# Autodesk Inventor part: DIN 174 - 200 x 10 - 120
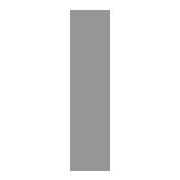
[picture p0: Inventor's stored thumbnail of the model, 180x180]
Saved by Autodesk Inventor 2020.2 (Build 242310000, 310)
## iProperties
_CCFamilyMember: 356
_CCFamilyDisplayName: DIN EN 10278 - Flachstahl
_FrameMemberDoc: Frame Member File
_Version: 15.0.0
_GetPNFromCC: 1
IsCustomPart: 1
Created: 2019-01
Part Number: DIN 174 - 200 x 10 - 120
Material: Stahl, weich
Description: Flachstahl
Document SubType Name: Modeling
Standard: DIN
Designer: lutzd
Standards Organization: DIN
Language: de-DE
Size Designation: 200 x 10
Categories: <MemberInstance><Categories><Category DisplayName="Profile" InternalName="089c4875-fa83-4c05-b084-43b9cc11f5ed" Mnemonic="GRDR"><CategoryParameter DisplayName="
Stock Number: 200 x 10
Mass: 1836.44 g
Surface Area: 533.912 cm^2
Volume: 233.941 cm^3
Density: 7.85 g/cm^3
Appearance: Semi-Polished(8)
G_L: 120,000 mm
G_W: 10,000 mm
G_H: 200,000 mm
+550D6204-CB8D-4930-8D8D-F81F26F66AC1+SCHNITTDETAIL1: Schnittwinkel 90,00 grd
DocNumber: ADSK-014385
Folder: .
Mass: 1,836 kg
VLT_Material: Stahl, weich
Dimensions: 200x10x120 mm
Title: Profil-Bauteil
Author: lutzd
Revision Number: -
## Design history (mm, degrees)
node "Startebene"
node "Endebene"
sketch "Skizze"
  geometry: L1 (5, -100)-(-5, -100); L2 (-5, -100)-(-5, 100); L3 (-5, 100)-(5, 100); L4 (5, 100)-(5, -100); L5 (-6, 0)-(8, 0); L6 (0, -30)-(0, 40); L7 (0, 140)-(0, -140) reference; L8 (-9.2, 0)-(13.2, 0) reference
  constraints: 12 end point, 2 collinear, 2 parallel, 1 horizontal, 1 perpendicular
  dimensions: "d0" = 200 distance between parallel lines of L3 L1 (= G_W); "d1" = 10 distance between parallel lines of L4 L2 (= G_H); "d4" = 5 distance between parallel lines of L6 L4 (= 0.5 x d1); "d5" = 100 distance between parallel lines of L5 L3 (= 0.5 x d0)
extrude "Körper" new body sketch "Skizze" stored distance "d2" = 120 (= G_L); taper "d3" = 0 deg
node "Driven Length"
  sketch "Sketch3"
    geometry: L1 (0, 0)-(10, 0) reference
    constraints: 2 end point, 1 horizontal
  workplane "Work Plane3"
  sketch "Sketch4"
    geometry: L1 (-2, 1960)-(12, 1960) reference; L2 (-2, 2080)-(12, 2080) reference
    dimensions: "d9" = 120 distance between parallel lines of L1 L2 (derived)
workplane "Arbeitsebene4"
feature "Trennen1"
fillet "Rundung1" dims "d10" = 50
sketch "Skizze5"
  geometry: L1 (85, -77)-(85, -177); L2 (120, -200)-(120, 0) reference; L3 (0, 0)-(120, 0) reference; 3 further points
  constraints: 2 end point, 1 coincident, 1 midpoint, 1 vertical
  dimensions: "d11" = 35 distance between parallel lines of L2 L1; "d12" = 100 distance of L1.start L1.end; "d20" = 77 distance from line of L3 L1.start
hole "Bohrung1" sketch "Skizze5" at (85, -77), (85, -177) diameter "d13" = 6.647; stored, may be unused: countersink angle "d17" = 90 deg, drill point angle "d19" = 118 deg; dims "d14" = 16, "d15" = 17.3, "d16" = 2, "d18" = 22.2
body "Solid1"
other parameters: "G_W" = 200 [user parameter; used in 1 equation term], "G_H" = 10 [user parameter; used in 1 equation term], "G_L" = 120 (= d9) [user parameter; used in 1 equation term], "G_OFFSET_END" = 0 [user parameter; used in 1 equation term], "d8" = 90 deg
